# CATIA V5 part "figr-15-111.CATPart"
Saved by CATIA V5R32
Part number: Part1
Bounding box of the stored display mesh (mm): x 0.737 to 206.429, y 0 to 112.04, z -6 to 2
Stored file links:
  D:\PROJECTS\Project 2022\CATIA V5 6R 2022\Resources\Part Files\c15_catia_v5_6r2022_prt\figr-15-111.CATPart
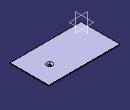
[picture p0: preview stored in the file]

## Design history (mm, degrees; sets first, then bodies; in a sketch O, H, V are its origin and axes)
SheetMetalParameters1: Thickness 2, BendRadius 4, KFactor 0.400515 {= log(min(100,max(20*SheetMetalParameters1.BendRadius,SheetMetalParameters1.Thickness)/SheetMetalParameters1.Thickness))/log(100)/2}, ReliefRadialLength 1, ReliefAxialLength 2, MinimumBendRadius 0
Body1 (main body)
  Sketch1 on xy-plane, origin (0, 0, 0), H (1, 0, 0), V (0, 1, 0)
    line L1 (0.7372, 112.0403) -> (206.4285, 112.0403)
    line L2 (206.4285, 112.0403) -> (206.4285, 0)
    line L3 (206.4285, 0) -> (0.7372, 0)
    line L4 (0.7372, 0) -> (0.7372, 112.0403)
    horizontal: L1 H, L3 H
    vertical: L2 V, L4 V
  Wall1: Thickness 2, Profile Sketch1, OffsetValue 0
  Sketch2 on face of Wall1, origin (152.409, 60.7083, 2), H (1, 0, 0), V (0, 1, 0)
    point P1 (0, 0)
  d_Stamp1: KFacteur 0.400515 {= SheetMetalParameters1.KFactor}, NewRoot_AttribNormalisation "No Standard", Stamp_FilletActivity true, Stamp_FilletRadius 2, Stamp_IntersectFilletRadius 2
